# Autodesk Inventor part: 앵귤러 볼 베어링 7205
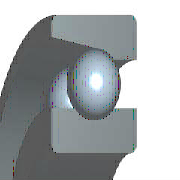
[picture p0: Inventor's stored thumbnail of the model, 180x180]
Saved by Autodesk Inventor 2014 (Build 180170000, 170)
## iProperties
Created: 2012-02
Part Number: 앵귤러 볼 베어링 7205
Material: 강철, 연강
Description: 앵귤러 콘택트 볼 베어링
Document SubType Name: Modeling
Standard: KS B 2024
Designer: mduedu
Standards Organization: KS
Language: ko-KR
Size Designation: 7205 - 25 x 52 x 15
Categories: <MemberInstance><Categories><Category DisplayName="샤프트 부품" InternalName="7f7aeb1f-a693-4053-b835-cee3144e0d98" Mnemonic="SHFT"><Category DisplayName="베어링" Inter
Density: 1 g/cm^3
Appearance: 노란색
IsCustomPart: 1
Author: mduedu
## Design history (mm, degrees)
sketch "스케치" dims "d1" = 7.02 (= -0.26 x WD + 0.26 x BD)
  geometry: L1 (3.99, 19.25)-(11.01, 19.25); L2 (7.5, 22.76)-(7.5, 15.74); L3 (0, 16.901)-(4.892, 16.901); L4 (0, 12.5)-(15, 12.5); L5 (8.11, 22.707)-(0, 24.137); L6 (15, 16.901)-(15, 12.5); L7 (15, 16.901)-(10.108, 16.901); L8 (15, 21.599)-(10.108, 21.599); L9 (15, 21.599)-(15, 26); L10 (0, 26)-(15, 26); L11 (-2.4, 0)-(14.4, 0) reference; L12 (0, -1.44)-(0, 8.99) reference; 1 further point
  constraints: 20 end point, 4 point on line, 3 symmetric about line, 2 midpoint, 2 parallel, 1 perpendicular, 14 other
  dimensions: "d0" = 10 deg angle of L8 L5; "d11" = 25 diameter of L4 L11 (= WD); "d12" = 52 diameter of L10 L11 (= BD); "d13" = 15 distance between parallel lines of L6 L12 (= KB); "d14" = 33.802 diameter of L7 L11 (= 0.326 x BD + 0.674 x WD)
revolve "본체" stored, may be unused: angle "d6" = 90 deg
revolve "볼" stored, may be unused: angle "d8" = 90 deg
pattern_circular "IDS_ARRAYBALL[SIMPL:T]" dims angle "d4" = 360 deg
body "Solid1"
fillet "모깎기1" dims "d2" = 1 (= KRS)
other parameters: "WD" = 25 [user parameter; used in 5 equation terms], "BD" = 52 [user parameter; used in 5 equation terms], "KB" = 15 [user parameter; used in 1 equation term], "KRS" = 1 [user parameter; used in 1 equation term], "d5" = 0, "d7" = 0, "d9" = 0, "d15" = 0, "d16" = 0, "BC0" = 1.02e+07 [user parameter], "BBA" = 30 deg [user parameter], "BC" = 1.56e+07 [user parameter], "KR1S" = 0.6 [user parameter], "BR" = 26 (= 0.5 x BD) [user parameter], "WR" = 12.5 (= 0.5 x WD) [user parameter]
